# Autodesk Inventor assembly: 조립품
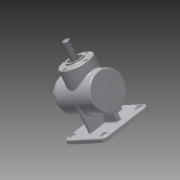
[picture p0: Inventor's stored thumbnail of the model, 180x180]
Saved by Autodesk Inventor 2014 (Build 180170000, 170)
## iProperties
Created: 2015-07
Part Number: 조립품
Document SubType Name: Assembly
Designer: user
Author: user
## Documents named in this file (13)
- C:\Users\user\Desktop\450706v1003\조립품.iam
- C:\Users\user\Desktop\450706v1003\본체.ipt
- C:\Users\user\Desktop\450706v1003\커버.ipt
- C:\Users\user\Desktop\450706v1003\M4.ipt
- C:\Users\user\Desktop\450706v1003\베어링 6203.ipt
- C:\Users\user\Desktop\450706v1003\메인 축.ipt
- 메인 축.ipt
- C:\Users\user\Desktop\450706v1003\서브 축.ipt
- 서브 축.ipt
- C:\Users\user\Desktop\450706v1003\키 4x4.ipt
- C:\Users\user\Desktop\450706v1003\키 5x5.ipt
- C:\Users\user\Desktop\450706v1003\서브 베벨기어.ipt
- C:\Users\user\Desktop\450706v1003\메인 베벨기어.ipt
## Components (8 placed, 1 different names)
1. M4:2 — Insert:6
2. M4:3
3. M4:4
4. M4:5
5. M4:1 — Insert:5
6. M4:6
7. M4:7
8. M4:8
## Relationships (2: Insert 2)
- Insert:5: M4:1
- Insert:6: M4:2
